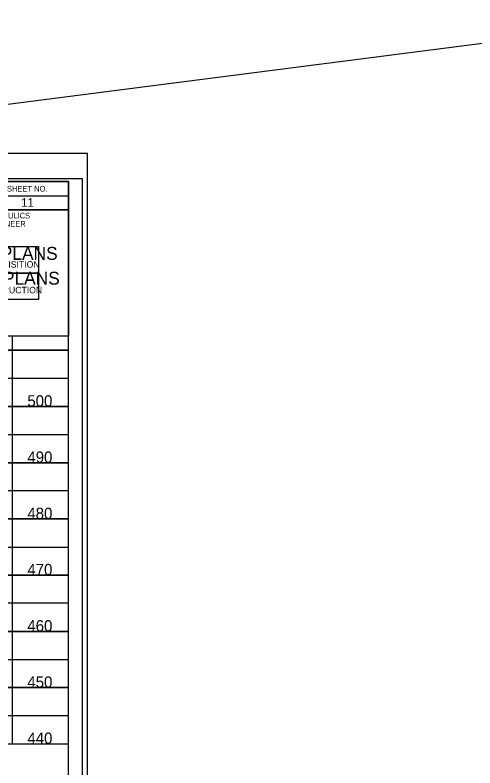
# Model space of a CAD drawing. Extents: x 571503 to 593215, y -77195 to -51828.
# Drawn here: x 587378 to 587787, y -53168 to -52498 of the extents above; entities that cross this region are included whole.
import ezdxf

# ---------------------------------------------------------------- set-up
doc = ezdxf.new("R2010")
doc.units = 0
for name, color, linetype in [('Exist Vertical Profile Vertical Axis Label', 7, 'Continuous'), ('Prop PFL Text', 7, 'Continuous'), ('Sheet Data Field CELL', 7, 'Continuous'), ('Sheet DOT Grid CELL', 7, 'Continuous'), ('Sheet Plot Border Inside CELL', 7, 'Continuous'), ('Sheet Plot Border Outside CELL', 7, 'Continuous'), ('Sheet Profile CELL', 7, 'Continuous'), ('Sheet Profile Grid Major CELL', 7, 'Continuous'), ('Sheet Profile Grid Middle CELL', 7, 'Continuous'), ('Sheet Sticker Incomplete CELL', 7, 'Continuous'), ('Sheet Sticker Preliminary CELL', 7, 'Continuous')]:
    doc.layers.add(name, color=color, linetype=linetype)

msp = doc.modelspace()

# ---------------------------------------------------------------- linework, layer by layer
at = {"layer": 'Prop PFL Text'}
msp.add_line((571799.62, -54572.45), (593215.36, -51828.37), dxfattribs=at)
at = {"layer": 'Sheet DOT Grid CELL'}
for p, q in [((587425.93, -53146.12), (587425.93, -52783.67)), ((585925.93, -52796.12), (587425.93, -52796.12)), ((587425.93, -52796.12), (585925.93, -52796.12)), ((585925.93, -52846.12), (587425.93, -52846.12)), ((587425.93, -52846.12), (586575.93, -52846.12)), ((587425.93, -52896.12), (585925.93, -52896.12)), ((586575.93, -52896.12), (587425.93, -52896.12)), ((585925.93, -52946.12), (587425.93, -52946.12)), ((587425.93, -52946.12), (585925.93, -52946.12)), ((585925.93, -52996.12), (587425.93, -52996.12)), ((587425.93, -52996.12), (585925.93, -52996.12)), ((585925.93, -53046.12), (587425.93, -53046.12)), ((587425.93, -53046.12), (585925.93, -53046.12)), ((585925.93, -53096.12), (587425.93, -53096.12)), ((587425.93, -53096.12), (585925.93, -53096.12))]:
    msp.add_line(p, q, dxfattribs=at)
at = {"layer": 'Sheet Plot Border Inside CELL'}
msp.add_lwpolyline([(585771.93, -53698.67), (587438.43, -53698.67), (587438.43, -52643.57), (585771.93, -52643.57)], close=True, dxfattribs=at)
at = {"layer": 'Sheet Plot Border Outside CELL'}
msp.add_lwpolyline([(585758.93, -53721.12), (587442.93, -53721.12), (587442.93, -52621.12), (585758.93, -52621.12)], close=True, dxfattribs=at)
at = {"layer": 'Sheet Profile CELL'}
for p, q in [((587442.93, -52621.12), (585758.93, -52621.12)), ((587225.88, -52658.67), (587425.93, -52658.67)), ((585925.93, -53146.12), (587425.93, -53146.12))]:
    msp.add_line(p, q, dxfattribs=at)
for points in [[(587425.93, -52646.12), (585925.93, -52646.12), (585925.93, -53696.12), (587425.93, -53696.12)], [(587225.88, -52646.12), (587425.93, -52646.12), (587425.93, -52671.17), (587225.88, -52671.17)], [(587325.93, -52671.17), (587425.93, -52671.17), (587425.93, -52783.67), (587325.93, -52783.67)]]:
    msp.add_lwpolyline(points, close=True, dxfattribs=at)
at = {"layer": 'Sheet Profile Grid Major CELL'}
for points in [[(587225.93, -52746.12), (585925.93, -52746.12), (585925.93, -52796.12), (587425.93, -52796.12)], [(587375.93, -52783.67), (587375.93, -53146.12), (587425.93, -53146.12), (587425.93, -52796.12)], [(587425.93, -52846.12), (585925.93, -52846.12), (585925.93, -52896.12), (587425.93, -52896.12)], [(587425.93, -52946.12), (585925.93, -52946.12), (585925.93, -52996.12), (587425.93, -52996.12)], [(587425.93, -53046.12), (585925.93, -53046.12), (585925.93, -53046.12), (585925.93, -53096.12), (587425.93, -53096.12)]]:
    msp.add_lwpolyline(points, dxfattribs=at)
at = {"layer": 'Sheet Profile Grid Middle CELL'}
for points in [[(587425.93, -52821.12), (585925.93, -52821.12), (585925.93, -52871.12), (587250.93, -52871.12)], [(587250.93, -52871.12), (587425.93, -52871.12)], [(587425.93, -52921.12), (585925.93, -52921.12), (585925.93, -52971.12), (587425.93, -52971.12)], [(587425.93, -53021.12), (585925.93, -53021.12), (585925.93, -53071.12), (587425.93, -53071.12)], [(587425.93, -53121.12), (585925.93, -53121.12)]]:
    msp.add_lwpolyline(points, dxfattribs=at)
at = {"layer": 'Sheet Sticker Incomplete CELL'}
msp.add_lwpolyline([(587252.43, -52727.4), (587252.43, -52703.9), (587399.43, -52703.9), (587399.43, -52727.4)], close=True, dxfattribs=at)
at = {"layer": 'Sheet Sticker Preliminary CELL'}
msp.add_lwpolyline([(587252.43, -52750.9), (587252.43, -52727.4), (587399.43, -52727.4), (587399.43, -52750.9)], close=True, dxfattribs=at)

# ---------------------------------------------------------------- texts
at = {"layer": 'Exist Vertical Profile Vertical Axis Label'}
for s, p in [('500', (587389.36, -52846.12)), ('490', (587389.36, -52896.12)), ('480', (587389.36, -52946.12)), ('470', (587389.36, -52996.12)), ('460', (587389.36, -53046.12)), ('450', (587389.36, -53096.12)), ('440', (587389.36, -53146.12))]:
    msp.add_text(s, height=10, dxfattribs=at).set_placement(p)
at = {"layer": 'Sheet Data Field CELL'}
msp.add_text('11 ', height=7.75, dxfattribs=at).set_placement((587383.76, -52668.51))
at = {"layer": 'Sheet Profile CELL'}
for s, p in [('SHEET NO.', (587371.24, -52654.91)), ('HYDRAULICS', (587348.74, -52678.86)), ('ENGINEER', (587352.99, -52686.21))]:
    msp.add_text(s, height=5, dxfattribs=at).set_placement(p)
at = {"layer": 'Sheet Sticker Incomplete CELL'}
for s, height, p in [('INCOMPLETE PLANS', 11.52, (587261.39, -52715.69)), ('DO NOT USE FOR R/W ACQUISITION', 5.76, (587264.64, -52722.64))]:
    msp.add_text(s, height=height, dxfattribs=at).set_placement(p)
at = {"layer": 'Sheet Sticker Preliminary CELL'}
for s, height, p in [('PRELIMINARY PLANS', 11.52, (587258.94, -52737.74)), ('DO NOT USE FOR CONSTRUCTION', 5.76, (587272.04, -52745.44))]:
    msp.add_text(s, height=height, dxfattribs=at).set_placement(p)

doc.saveas('drawing.dxf')
